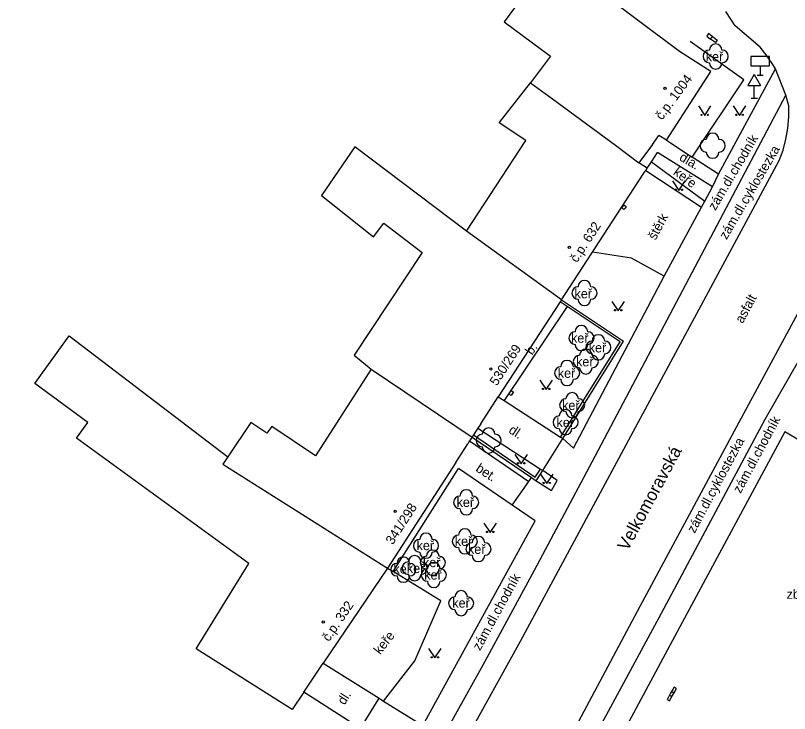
# Model space of a CAD drawing. Extents: x -577457 to -568404, y -1208466 to -1201387.
# Drawn here: x -568987 to -568925.4, y -1204374.7 to -1204319.2 of the extents above; entities that cross this region are included whole.
import ezdxf

# ---------------------------------------------------------------- set-up
doc = ezdxf.new("R2010")
doc.units = 0
for name, color, linetype in [('BUDOVY_MĚŘ', 7, 'Continuous'), ('BUDOVY_NEMĚŘ', 7, 'Continuous'), ('NÁZVY_ULIC_TOK_SMĚR', 7, 'Continuous'), ('OBVOD_PILÍŘE', 7, 'Continuous'), ('POMOC_POPIS', 7, 'Continuous'), ('ROZHRANÍ_PLOCH', 7, 'Continuous'), ('ZELEŇ', 7, 'Continuous'), ('ZN_BUDOV', 7, 'Continuous'), ('ZN_DOPLŇKOVÉ', 7, 'Continuous'), ('ZN_KULTUR', 7, 'Continuous'), ('Č_POPIS_ORIENT', 7, 'Continuous')]:
    doc.layers.add(name, color=color, linetype=linetype)

msp = doc.modelspace()

# ---------------------------------------------------------------- linework, layer by layer
at = {"layer": 'BUDOVY_MĚŘ'}
for points in [[(-568934.17, -1204322.04), (-568944.26, -1204314.47)], [(-568931.66, -1204323.64), (-568934.17, -1204322.04)], [(-568935.19, -1204329.11), (-568931.66, -1204323.64)], [(-568935.19, -1204329.11), (-568935.81, -1204328.72)], [(-568936.32, -1204329.43), (-568937.39, -1204330.9)], [(-568936.73, -1204331.33), (-568937.39, -1204330.9)], [(-568936.99, -1204331.73), (-568936.84, -1204331.5)], [(-568936.84, -1204331.5), (-568936.73, -1204331.33)], [(-568943.54, -1204341.78), (-568938.48, -1204334.01)], [(-568943.65, -1204341.95), (-568948.57, -1204349.49)], [(-568943.54, -1204341.78), (-568943.65, -1204341.95)], [(-568949.96, -1204351.64), (-568950.2, -1204352)], [(-568950.55, -1204352.53), (-568950.66, -1204352.7)], [(-568950.2, -1204352), (-568950.55, -1204352.53)], [(-568950.86, -1204353.01), (-568951, -1204353.23)], [(-568950.66, -1204352.7), (-568950.86, -1204353.01)], [(-568951.96, -1204354.71), (-568957.39, -1204363.13)], [(-568957.39, -1204363.13), (-568962.49, -1204370.68)], [(-568964.04, -1204372.97), (-568964.97, -1204374.35)]]:
    msp.add_lwpolyline(points, dxfattribs=at)
at = {"layer": 'BUDOVY_NEMĚŘ'}
for points in [[(-568944.26, -1204314.47), (-568948.11, -1204319.7), (-568944.42, -1204322.41), (-568946.01, -1204324.53), (-568944.27, -1204325.81), (-568939.26, -1204329.49), (-568937.39, -1204330.9)], [(-568951.11, -1204336.33), (-568946.37, -1204329.13), (-568948.5, -1204327.73), (-568946.01, -1204324.53)], [(-568951.11, -1204336.33), (-568959.97, -1204329.64), (-568962.64, -1204333.5), (-568958.49, -1204336.78), (-568957.68, -1204335.7), (-568954.63, -1204338.03), (-568960.04, -1204346.18), (-568958.68, -1204347.3)], [(-568943.54, -1204341.78), (-568951.11, -1204336.33)], [(-568964.97, -1204374.35), (-568972.59, -1204369.53), (-568968.4, -1204362.76), (-568982.1, -1204352.78), (-568981.2, -1204351.53), (-568985.42, -1204348.44), (-568982.68, -1204344.66), (-568970.07, -1204354.26)], [(-568958.68, -1204347.3), (-568963.11, -1204354.2), (-568966.58, -1204351.85), (-568966.98, -1204352.38), (-568968.26, -1204351.54), (-568970.07, -1204354.26)], [(-568958.68, -1204347.3), (-568950.66, -1204352.7)], [(-568970.07, -1204354.26), (-568970.47, -1204354.86), (-568957.39, -1204363.13)]]:
    msp.add_lwpolyline(points, dxfattribs=at)
at = {"layer": 'OBVOD_PILÍŘE'}
for points in [[(-568931.7, -1204320.74), (-568931.85, -1204320.63), (-568932, -1204320.84), (-568931.69, -1204321.07), (-568931.54, -1204320.86), (-568931.7, -1204320.74)], [(-568931.35, -1204321), (-568931.16, -1204321.14), (-568931.3, -1204321.34), (-568931.69, -1204321.07), (-568931.54, -1204320.86), (-568931.35, -1204321)], [(-568938.49, -1204334.49), (-568938.58, -1204334.62), (-568938.76, -1204334.5), (-568938.59, -1204334.24), (-568938.4, -1204334.36), (-568938.49, -1204334.49)], [(-568947.46, -1204349.27), (-568947.55, -1204349.4), (-568947.73, -1204349.28), (-568947.55, -1204349.01), (-568947.37, -1204349.14), (-568947.46, -1204349.27)], [(-568934.7, -1204372.77), (-568934.79, -1204372.93), (-568934.6, -1204373.04), (-568934.4, -1204372.69), (-568934.59, -1204372.58), (-568934.7, -1204372.77)], [(-568935.04, -1204373.37), (-568935.15, -1204373.56), (-568934.96, -1204373.67), (-568934.76, -1204373.32), (-568934.95, -1204373.21), (-568935.04, -1204373.37)], [(-568934.87, -1204373.07), (-568934.95, -1204373.21), (-568934.76, -1204373.32), (-568934.6, -1204373.04), (-568934.79, -1204372.93), (-568934.87, -1204373.07)]]:
    msp.add_lwpolyline(points, dxfattribs=at)
at = {"layer": 'ROZHRANÍ_PLOCH'}
for points in [[(-568926.53, -1204323.43), (-568926.68, -1204323.17), (-568927.18, -1204322.41), (-568927.75, -1204321.71), (-568929.74, -1204320.02), (-568930.47, -1204318.88)], [(-568931.06, -1204331.81), (-568926.53, -1204323.43)], [(-568925.72, -1204325.51), (-568926.53, -1204323.43)], [(-568941.11, -1204354.66), (-568925.72, -1204325.51)], [(-568925.48, -1204326.36), (-568925.72, -1204325.51)], [(-568925.47, -1204327.25), (-568925.48, -1204326.36)], [(-568925.54, -1204328.14), (-568925.47, -1204327.25)], [(-568925.7, -1204329.02), (-568925.54, -1204328.14)], [(-568925.92, -1204329.88), (-568925.7, -1204329.02)], [(-568936.39, -1204330.81), (-568935.9, -1204330.07)], [(-568931.55, -1204332.82), (-568935.9, -1204330.07)], [(-568926.23, -1204330.72), (-568925.92, -1204329.88)], [(-568986.96, -1204449.86), (-568983.6, -1204444.85), (-568969.76, -1204423.38), (-568960.92, -1204409.65), (-568953.77, -1204398.59), (-568948.99, -1204390.8), (-568944.8, -1204383.61), (-568940.67, -1204376.12), (-568935.59, -1204366.71), (-568927.34, -1204351.28), (-568915.4, -1204330.46)], [(-568946.8, -1204368.93), (-568926.23, -1204330.72)], [(-568936.73, -1204331.33), (-568936.39, -1204330.81)], [(-568931.06, -1204331.81), (-568933.15, -1204330.44)], [(-568936.84, -1204331.5), (-568932.41, -1204334.43)], [(-568931.55, -1204332.82), (-568931.06, -1204331.81)], [(-568932.16, -1204333.95), (-568931.55, -1204332.82)], [(-568919.91, -1204333.86), (-568928.89, -1204350.5), (-568937.31, -1204366.16), (-568942.2, -1204375.31), (-568942.83, -1204376.46), (-568946.59, -1204383.17), (-568950.6, -1204390.07), (-568951.12, -1204390.92), (-568955.31, -1204397.74), (-568956.94, -1204400.23), (-568962.44, -1204408.79), (-568971, -1204422.09), (-568984.27, -1204442.65)], [(-568932.41, -1204334.43), (-568932.16, -1204333.95)], [(-568935.37, -1204339.91), (-568932.41, -1204334.43)], [(-568935.37, -1204339.91), (-568937.97, -1204338.49), (-568941.08, -1204338.01)], [(-568942.58, -1204353.58), (-568935.37, -1204339.91)], [(-568943.09, -1204342.32), (-568948.11, -1204349.79)], [(-568948.57, -1204349.49), (-568948.11, -1204349.79)], [(-568948.11, -1204349.79), (-568943.62, -1204352.71)], [(-568950.2, -1204352), (-568945.21, -1204355.25)], [(-568924.58, -1204352.99), (-568925.8, -1204352.28), (-568933.95, -1204367.44), (-568939.17, -1204377.17), (-568939.95, -1204378.5)], [(-568950.86, -1204353.01), (-568946.15, -1204356.22)], [(-568943.45, -1204352.82), (-568942.58, -1204353.58)], [(-568968.27, -1204401.72), (-568963.57, -1204394.3), (-568954.57, -1204379.42), (-568949.78, -1204370.82), (-568945.7, -1204363.27), (-568941.11, -1204354.66)], [(-568956.94, -1204363.39), (-568951.74, -1204355.21)], [(-568947.46, -1204358.12), (-568951.74, -1204355.21)], [(-568945.57, -1204356.17), (-568944.34, -1204356.95), (-568943.89, -1204356.14), (-568945.04, -1204355.36)], [(-568947.46, -1204358.12), (-568946.15, -1204356.22)], [(-568946.15, -1204356.22), (-568945.94, -1204355.92)], [(-568957.69, -1204373.7), (-568954.56, -1204375.64), (-568945.64, -1204359.37), (-568947.46, -1204358.12)], [(-568957.39, -1204363.13), (-568956.94, -1204363.39)], [(-568951.18, -1204376.82), (-568946.8, -1204368.93)], [(-568962.49, -1204370.68), (-568958.03, -1204373.47)], [(-568959.54, -1204375.88), (-568964.04, -1204372.97)], [(-568959.54, -1204375.88), (-568958.03, -1204373.47)], [(-568958.03, -1204373.47), (-568957.69, -1204373.7)]]:
    msp.add_lwpolyline(points, dxfattribs=at)
at = {"layer": 'ZELEŇ'}
for points in [[(-568936.39, -1204330.81), (-568932.16, -1204333.95)], [(-568957.69, -1204373.7), (-568955.2, -1204370.5), (-568953.14, -1204365.72), (-568956.94, -1204363.39)]]:
    msp.add_lwpolyline(points, dxfattribs=at)
for centre in [(-568931.29, -1204322.44), (-568931.53, -1204329.54), (-568941.72, -1204341.25), (-568941.96, -1204344.83), (-568940.61, -1204345.57), (-568941.61, -1204346.69), (-568943.1, -1204347.61), (-568942.7, -1204350.16), (-568943.22, -1204351.52), (-568949.34, -1204352.97), (-568951.12, -1204357.89), (-568951.23, -1204360.99), (-568954.32, -1204361.34), (-568950.15, -1204361.6), (-568953.78, -1204362.68), (-568956.12, -1204363.24), (-568955.22, -1204363.12), (-568953.7, -1204363.66), (-568951.52, -1204365.91)]:
    msp.add_circle(centre, 0.0005, dxfattribs=at)
for centre, start, end in [((-568931.29, -1204321.94), 0, 179.99999), ((-568931.79, -1204322.44), 89.99999, 269.99999), ((-568930.79, -1204322.44), 270, 89.99999), ((-568931.29, -1204322.94), 179.99999, 359.99999), ((-568931.53, -1204329.04), 0, 179.99999), ((-568932.03, -1204329.54), 89.99999, 269.99999), ((-568931.03, -1204329.54), 270, 89.99999), ((-568931.53, -1204330.04), 179.99999, 359.99999), ((-568941.72, -1204340.75), 0, 179.99999), ((-568942.22, -1204341.25), 89.99999, 269.99999), ((-568941.22, -1204341.25), 270, 89.99999), ((-568941.72, -1204341.75), 179.99999, 359.99999), ((-568941.96, -1204344.33), 0, 179.99999), ((-568942.46, -1204344.83), 89.99999, 269.99999), ((-568941.46, -1204344.83), 270, 89.99999), ((-568941.11, -1204345.57), 89.99999, 269.99999), ((-568940.61, -1204345.07), 0, 179.99999), ((-568940.11, -1204345.57), 270, 89.99999), ((-568941.96, -1204345.33), 179.99999, 359.99999), ((-568941.61, -1204346.19), 0, 179.99999), ((-568942.11, -1204346.69), 89.99999, 269.99999), ((-568940.61, -1204346.07), 179.99999, 359.99999), ((-568941.11, -1204346.69), 270, 89.99999), ((-568943.1, -1204347.11), 0, 179.99999), ((-568943.6, -1204347.61), 89.99999, 269.99999), ((-568942.6, -1204347.61), 270, 89.99999), ((-568941.61, -1204347.19), 179.99999, 359.99999), ((-568943.1, -1204348.11), 179.99999, 359.99999), ((-568942.7, -1204349.66), 0, 179.99999), ((-568943.2, -1204350.16), 89.99999, 269.99999), ((-568942.2, -1204350.16), 270, 89.99999), ((-568943.22, -1204351.02), 0, 179.99999), ((-568942.7, -1204350.66), 179.99999, 359.99999), ((-568943.72, -1204351.52), 89.99999, 269.99999), ((-568942.72, -1204351.52), 270, 89.99999), ((-568949.84, -1204352.97), 89.99999, 269.99999), ((-568949.34, -1204352.47), 0, 179.99999), ((-568948.84, -1204352.97), 270, 89.99999), ((-568943.22, -1204352.02), 179.99999, 359.99999), ((-568949.34, -1204353.47), 179.99999, 359.99999), ((-568951.62, -1204357.89), 89.99999, 269.99999), ((-568951.12, -1204357.39), 0, 179.99999), ((-568950.62, -1204357.89), 270, 89.99999), ((-568951.12, -1204358.39), 179.99999, 359.99999), ((-568954.32, -1204360.84), 0, 179.99999), ((-568951.73, -1204360.99), 89.99999, 269.99999), ((-568951.23, -1204360.49), 0, 179.99999), ((-568950.73, -1204360.99), 270, 89.99999), ((-568954.82, -1204361.34), 89.99999, 269.99999), ((-568953.82, -1204361.34), 270, 89.99999), ((-568950.65, -1204361.6), 89.99999, 269.99999), ((-568950.15, -1204361.1), 0, 179.99999), ((-568949.65, -1204361.6), 270, 89.99999), ((-568953.78, -1204362.18), 0, 179.99999), ((-568951.23, -1204361.49), 179.99999, 359.99999), ((-568956.12, -1204362.74), 0, 179.99999), ((-568955.22, -1204362.62), 0, 179.99999), ((-568954.32, -1204361.84), 179.99999, 359.99999), ((-568954.28, -1204362.68), 89.99999, 269.99999), ((-568953.28, -1204362.68), 270, 89.99999), ((-568950.15, -1204362.1), 179.99999, 359.99999), ((-568956.62, -1204363.24), 89.99999, 269.99999), ((-568955.72, -1204363.12), 89.99999, 269.99999), ((-568955.62, -1204363.24), 270, 89.99999), ((-568954.72, -1204363.12), 270, 89.99999), ((-568953.7, -1204363.16), 0, 179.99999), ((-568955.22, -1204363.62), 179.99999, 359.99999), ((-568954.2, -1204363.66), 89.99999, 269.99999), ((-568953.78, -1204363.18), 179.99999, 359.99999), ((-568953.2, -1204363.66), 270, 89.99999), ((-568956.12, -1204363.74), 179.99999, 359.99999), ((-568953.7, -1204364.16), 179.99999, 359.99999), ((-568952.02, -1204365.91), 89.99999, 269.99999), ((-568951.52, -1204365.41), 0, 179.99999), ((-568951.02, -1204365.91), 270, 89.99999), ((-568951.52, -1204366.41), 179.99999, 359.99999)]:
    msp.add_arc(centre, 0.5, start, end, dxfattribs=at)
at = {"layer": 'ZN_BUDOV'}
for centre in [(-568935.31, -1204324.98), (-568942.93, -1204337.62), (-568949.16, -1204347.29), (-568956.77, -1204358.6), (-568962.49, -1204367.4)]:
    msp.add_circle(centre, 0.0875, dxfattribs=at)
at = {"layer": 'ZN_DOPLŇKOVÉ'}
for p, q in [((-568927.75, -1204323.19), (-568927.75, -1204323.94)), ((-568928.22, -1204323.884), (-568928.72, -1204324.75)), ((-568928.22, -1204323.884), (-568927.72, -1204324.75)), ((-568928, -1204323.94), (-568927.5, -1204323.94)), ((-568928.72, -1204324.75), (-568927.72, -1204324.75)), ((-568928.22, -1204325.75), (-568928.22, -1204324.75)), ((-568928.47, -1204325.75), (-568927.97, -1204325.75))]:
    msp.add_line(p, q, dxfattribs=at)
for points in [[(-568933.15, -1204330.44), (-568929.06, -1204324.29), (-568933.31, -1204321.25)], [(-568936.32, -1204329.43), (-568935.81, -1204328.72)], [(-568935.19, -1204329.11), (-568933.15, -1204330.44)], [(-568938.48, -1204334.01), (-568936.99, -1204331.73)], [(-568943.09, -1204342.32), (-568943.65, -1204341.95)], [(-568943.54, -1204341.78), (-568938.78, -1204344.97)], [(-568943.62, -1204352.71), (-568938.88, -1204345.14), (-568943.09, -1204342.32)], [(-568943.45, -1204352.82), (-568938.61, -1204345.08)], [(-568938.78, -1204344.97), (-568938.61, -1204345.08)], [(-568949.96, -1204351.64), (-568948.57, -1204349.49)], [(-568950.55, -1204352.53), (-568945.63, -1204355.89), (-568945.21, -1204355.25)], [(-568950.66, -1204352.7), (-568945.94, -1204355.92)], [(-568945.04, -1204355.36), (-568943.45, -1204352.82)], [(-568943.62, -1204352.71), (-568943.45, -1204352.82)], [(-568951.96, -1204354.71), (-568951, -1204353.23)], [(-568945.57, -1204356.17), (-568945.04, -1204355.36)], [(-568945.21, -1204355.25), (-568945.04, -1204355.36)], [(-568945.94, -1204355.92), (-568945.57, -1204356.17)], [(-568964.04, -1204372.97), (-568962.49, -1204370.68)]]:
    msp.add_lwpolyline(points, dxfattribs=at)
msp.add_lwpolyline([(-568928.5, -1204323.19), (-568927, -1204323.19), (-568927, -1204322.44), (-568928.5, -1204322.44)], close=True, dxfattribs=at)
at = {"layer": 'ZN_KULTUR'}
for points in [[(-568932.66, -1204326.38), (-568932.16, -1204327.13), (-568931.66, -1204326.38)], [(-568929.89, -1204326.38), (-568929.39, -1204327.13), (-568928.89, -1204326.38)], [(-568934.72, -1204332.34), (-568934.22, -1204333.09), (-568933.72, -1204332.34)], [(-568939.54, -1204341.92), (-568939.04, -1204342.67), (-568938.54, -1204341.92)], [(-568945.27, -1204348.17), (-568944.77, -1204348.92), (-568944.27, -1204348.17)], [(-568947.25, -1204354.08), (-568946.75, -1204354.83), (-568946.25, -1204354.08)], [(-568945.22, -1204355.65), (-568944.72, -1204356.4), (-568944.22, -1204355.65)], [(-568949.72, -1204359.54), (-568949.22, -1204360.29), (-568948.72, -1204359.54)], [(-568954.11, -1204369.51), (-568953.61, -1204370.26), (-568953.11, -1204369.51)]]:
    msp.add_lwpolyline(points, dxfattribs=at)
for centre in [(-568932.41, -1204327.08), (-568931.91, -1204327.08), (-568929.64, -1204327.08), (-568929.14, -1204327.08), (-568934.47, -1204333.04), (-568933.97, -1204333.04), (-568939.29, -1204342.62), (-568938.79, -1204342.62), (-568945.02, -1204348.87), (-568944.52, -1204348.87), (-568947, -1204354.78), (-568946.5, -1204354.78), (-568944.97, -1204356.35), (-568944.47, -1204356.35), (-568949.47, -1204360.24), (-568948.97, -1204360.24), (-568953.86, -1204370.21), (-568953.36, -1204370.21)]:
    msp.add_circle(centre, 0.05, dxfattribs=at)

# ---------------------------------------------------------------- texts
at = {"layer": 'NÁZVY_ULIC_TOK_SMĚR'}
msp.add_text('Velkomoravská', height=1, rotation=61.73414, dxfattribs=at).set_placement((-568938.28, -1204361.82))
at = {"layer": 'POMOC_POPIS'}
for s, rotation, p in [('zám.dl.chodník', 59.42122, (-568931.31, -1204334.74)), ('zám.dl.cyklostezka', 59.53003, (-568930.42, -1204337.05)), ('dla.', 329.42002, (-568934.24, -1204330.65)), ('štěrk', 61.62448, (-568936.07, -1204337.09)), ('asfalt', 61.6459, (-568929.14, -1204343.72)), ('b.', 56.09807, (-568945.88, -1204346.23)), ('zám.dl.chodník', 61.73758, (-568929.31, -1204357.23)), ('dl.', 326.89001, (-568947.81, -1204352.31)), ('zám.dl.cyklostezka', 61.75001, (-568932.96, -1204360.4)), ('bet.', 326.89001, (-568950.43, -1204355.36)), ('zám.dl.chodník', 61.26632, (-568950.02, -1204369.73)), ('dl.', 57.93056, (-568960.8, -1204374.05))]:
    msp.add_text(s, height=0.75, rotation=rotation, dxfattribs=at).set_placement(p)
msp.add_text('zbořeniště', height=0.75, dxfattribs=at).set_placement((-568925.65, -1204365.56))
at = {"layer": 'ZELEŇ'}
for p in [(-568932.08, -1204322.83), (-568942.51, -1204341.67), (-568942.79, -1204345.2), (-568941.38, -1204345.97), (-568942.39, -1204347.08), (-568943.84, -1204347.99), (-568943.5, -1204350.55), (-568943.94, -1204351.91), (-568951.89, -1204358.25), (-568952.03, -1204361.35), (-568955.07, -1204361.69), (-568950.98, -1204361.99), (-568954.56, -1204363.04), (-568956.91, -1204363.55), (-568955.84, -1204363.51), (-568954.46, -1204364.03), (-568952.23, -1204366.26)]:
    msp.add_text('keř', height=0.75, dxfattribs=at).set_placement(p)
for rotation, p in [(323.4129, (-568934.72, -1204331.78)), (52.11263, (-568957.96, -1204370.04))]:
    msp.add_text('keře', height=0.75, rotation=rotation, dxfattribs=at).set_placement(p)
at = {"layer": 'Č_POPIS_ORIENT'}
for s, rotation, p in [('č.p. 1004', 53.48, (-568935.56, -1204327.55)), ('č.p. 632', 56.91001, (-568942.32, -1204338.89)), ('530/269', 56.89998, (-568948.69, -1204348.68)), ('341/298', 57.17002, (-568956.96, -1204361.31)), ('č.p. 332', 55.95999, (-568962.03, -1204369.01))]:
    msp.add_text(s, height=0.75, rotation=rotation, dxfattribs=at).set_placement(p)

doc.saveas('drawing.dxf')
